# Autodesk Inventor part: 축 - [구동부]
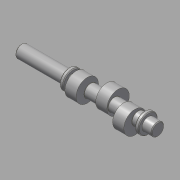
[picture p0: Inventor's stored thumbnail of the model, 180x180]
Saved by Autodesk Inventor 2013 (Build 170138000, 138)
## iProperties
Company: 한국ATC센터
Created: 2014-08
Part Number: 축 - [구동부]
Document SubType Name: Modeling
Designer: KYOUNG IL JANG
Density: 7.86 g/cm^3
Material: 강철, 연강
Mass: 516.584 g
Surface Area: 162.516 cm^2
Volume: 65.7231 cm^3
Author: KYOUNG IL JANG
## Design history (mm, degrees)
sketch "스케치1"
  geometry: L1 (-91.5, 0)-(91.5, 0); L2 (-91.5, 0)-(-91.5, 8.5); L3 (-91.5, 8.5)-(-27.5, 8.5); L4 (-27.5, 8.5)-(-27.5, 13); L5 (-27.5, 13)-(-22.5, 13); L6 (-22.5, 13)-(-22.5, 8.5); L7 (-22.5, 8.5)-(73.5, 8.5); L8 (73.5, 8.5)-(73.5, 13); L9 (73.5, 13)-(78.5, 13); L10 (78.5, 13)-(78.5, 8.5); L11 (78.5, 8.5)-(91.5, 8.5); L12 (91.5, 8.5)-(91.5, 0); 2 further points
  constraints: 24 end point, 5 parallel, 1 coincident, 1 horizontal, 1 midpoint, 1 perpendicular
  dimensions: "d0" = 183 distance of L1.start L1.end (derived); "d2" = 17 diameter of L3 L1; "d3" = 26 diameter of L5 L1; "d4" = 17 diameter of L7 L1; "d5" = 26 diameter of L9 L1; "d6" = 17 diameter of L11 L1; "d7" = 5 distance of L8.end L9.end; "d8" = 5 distance of L4.end L5.end; "d10" = 64 distance of L2.end L3.end; "d11" = 13 distance of L10.end L11.end; "d35" = 96 distance between parallel lines of L8 L6
revolve "회전1" sketch "스케치1" stored, may be unused: angle "d12" = 90 deg
node "작업 평면7"
sketch "스케치6"
  geometry: C1 r 15 at (0, 5); 1 further point
  constraints: 1 centre point, 1 vertical alignment
  dimensions: "d37" = 30 diameter of C1; "d38" = 5 distance of C1.centre point (0, 0)
extrude "돌출4" join sketch "스케치6" stored distance "d33" = 15; taper "d34" = 0 deg
node "작업 평면8"
sketch "스케치7"
  geometry: L1 (0, 0)-(-6.5, -11.258); L2 (0, 0)-(13, 0); C1 r 15 at (-2.5, -4.33); A1 r 13 centre (0, 0) between (-6.5, -11.258) and (13, 0) reference; 1 further point
  constraints: 4 end point, 2 point on circle, 1 centre point, 1 horizontal, 1 point on line
  dimensions: "d40" = 120 deg angle of L1 L2; "d41" = 30 diameter of C1; "d42" = 5 distance of point (0, 0) C1.centre
extrude "돌출5" join sketch "스케치7" stored distance "d43" = 15; taper "d44" = 0 deg
node "작업 평면9"
sketch "스케치8"
  geometry: L1 (0, 0)-(4.25, -7.361); L2 (0, 0)-(-8.5, 0); C1 r 15 at (2.5, -4.33); A1 r 8.5 centre (0, 0) between (4.25, -7.361) and (-8.5, 0) reference; 1 further point
  constraints: 4 end point, 2 point on circle, 1 centre point, 1 horizontal, 1 point on line
  dimensions: "d46" = 120 deg angle of L1 L2; "d47" = 30 diameter of C1; "d48" = 5 distance of point (0, 0) C1.centre
extrude "돌출6" join sketch "스케치8" stored distance "d49" = 15; taper "d50" = 0 deg
node "작업 평면3"
sketch "스케치5"
  geometry: L1 (32, 8.5)-(32, -8.5) reference; L2 (27.5, -2.5)-(14.5, -2.5); L3 (14.5, 2.5)-(27.5, 2.5); A1 r 2.5 centre (14.5, 0) between (14.5, 2.5) and (14.5, -2.5); A2 r 2.5 centre (27.5, 0) between (27.5, -2.5) and (27.5, 2.5); 4 further points
  constraints: 4 end point, 4 point on circle, 4 tangent, 2 centre point, 2 point on line, 1 horizontal alignment, 1 midpoint, 1 parallel, 1 perpendicular
  dimensions: "d23" = 5 distance between parallel lines of L3 L2; "d36" = 20 dimension on A1 L1; "d52" = 2 distance edge to line of A2 L1
extrude "돌출3" cut sketch "스케치5" distance "d25" = 3; taper "d26" = 0 deg
chamfer "모따기1" distance "d27" = 1; stored, may be unused: second distance "d28" = 2, angle "d29" = 45 deg
fillet "모깎기1" dims "d51" = 0.3
chamfer "모따기2" distance "d53" = 1; stored, may be unused: second distance "d54" = 2, angle "d55" = 45 deg
node "작업 평면10"
node "솔리드1"
other parameters: "d39" = -32, "d45" = 32
